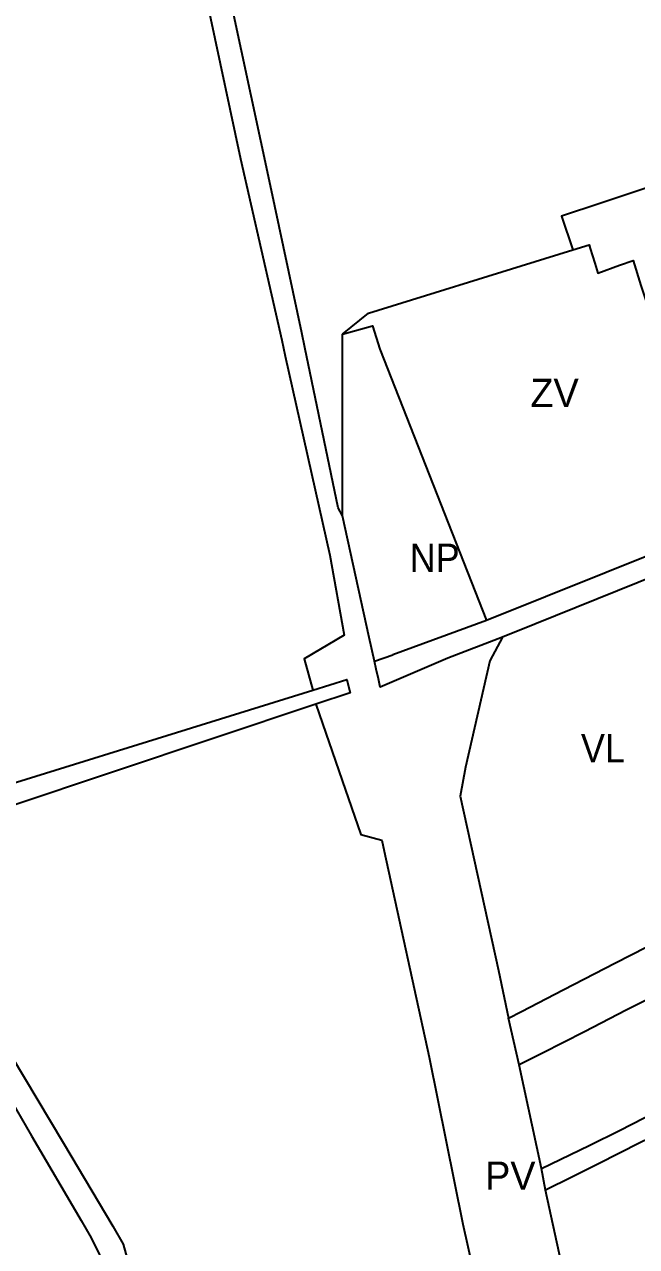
# Model space of a CAD drawing. Extents: x -650451 to -642268, y -1075216 to -1066610.
# Drawn here: x -648982 to -648658, y -1067753 to -1067105 of the extents above; entities that cross this region are included whole.
import ezdxf

# ---------------------------------------------------------------- set-up
doc = ezdxf.new("R2010")
doc.units = 0
doc.header["$LTSCALE"] = 6
doc.layers.add('1', color=7, linetype='Continuous', lineweight=35)
doc.layers.add('2', color=7, linetype='Continuous')
doc.layers.add('3', color=7, linetype='Continuous')

msp = doc.modelspace()

# ---------------------------------------------------------------- linework, layer by layer
at = {"layer": '1'}
for p, q in [((-648636.68, -1067380.92), (-648737.46, -1067421.52)), ((-648737.46, -1067421.52), (-648787.13, -1067439.58)), ((-648720.1, -1067657.12), (-648725.8, -1067632.36)), ((-648708.26, -1067712.07), (-648720.1, -1067657.12)), ((-648706.08, -1067723.56), (-648708.26, -1067712.07))]:
    msp.add_line(p, q, dxfattribs=at)
for points in [[(-648965.39, -1066723.15), (-648955.15, -1066770.11), (-648944.75, -1066815.41), (-648936.7, -1066852.52), (-648924.32, -1066909.55), (-648917.76, -1066942.65), (-648905.06, -1067006.7), (-648899.1, -1067033.34), (-648884.26, -1067099.63), (-648867.82, -1067176.66), (-648845.94, -1067272.85), (-648844.16, -1067281.37), (-648820.39, -1067386.83), (-648812.91, -1067429.16), (-648834.01, -1067441.81), (-648829.54, -1067458.42)], [(-648813.81, -1067365.91), (-648816.06, -1067361.71), (-648833.66, -1067276.77), (-648835.29, -1067268.93), (-648851.87, -1067191.04), (-648872.31, -1067095.5), (-648893.02, -1067002.5), (-648914.11, -1066907.05), (-648918.27, -1066888.41), (-648935.19, -1066812.53), (-648954.86, -1066720.16)], [(-649347.85, -1067077.78), (-649341.72, -1067086.34), (-649296.02, -1067150.21), (-649286.18, -1067163.62), (-649232.55, -1067236.73), (-649155.84, -1067339.24), (-649141.36, -1067361.14), (-649128.54, -1067392.42), (-649081.51, -1067517.84), (-649073.12, -1067526.28), (-649063.49, -1067529.27), (-649053.79, -1067527.97), (-648829.54, -1067458.42)], [(-648495.63, -1067161.363), (-648499.79, -1067162.97), (-648510.01, -1067144.84), (-648525.95, -1067150.5), (-648526.39, -1067149.8), (-648547.68, -1067156.93), (-648579.12, -1067167.45), (-648580.15, -1067164.76), (-648603.17, -1067172.45), (-648602.26, -1067175.2), (-648676.84, -1067200.16), (-648697.59, -1067207.11), (-648691.66, -1067224.94)], [(-648691.66, -1067224.94), (-648683.07, -1067222.28), (-648682.43, -1067224.18), (-648680.03, -1067231.91), (-648678.37, -1067237.22), (-648666.88, -1067233.11), (-648659.66, -1067230.53), (-648655.57, -1067243.76), (-648646.48, -1067271.25)], [(-648813.78, -1067269.55), (-648800.02, -1067258.42), (-648706.47, -1067229.51), (-648691.66, -1067224.94)], [(-648813.78, -1067269.55), (-648797.88, -1067265.22), (-648794.03, -1067277.5), (-648737.46, -1067421.52)], [(-648813.81, -1067365.91), (-648813.8, -1067322.02), (-648813.78, -1067269.55)], [(-648796.8, -1067443.1), (-648799.58, -1067430.4), (-648813.81, -1067365.91)], [(-648646.13, -1067396.91), (-648711.76, -1067423.39), (-648728.95, -1067430.33)], [(-648728.95, -1067430.33), (-648757.97, -1067441.51), (-648793.71, -1067456.88), (-648794.7, -1067452.46), (-648795.88, -1067447.21)], [(-648728.95, -1067430.33), (-648735.59, -1067442.88), (-648748.53, -1067499.3), (-648751.29, -1067514.57), (-648731.06, -1067607.06), (-648725.8, -1067632.36)], [(-648795.88, -1067447.21), (-648796.8, -1067443.1), (-648787.13, -1067439.58)], [(-648829.54, -1067458.42), (-648811.4, -1067452.79), (-648811.21, -1067453.52), (-648809.97, -1067458.52), (-648809.65, -1067459.77), (-648827.86, -1067465.86)], [(-648827.86, -1067465.86), (-649043.58, -1067537.95), (-649051.36, -1067541.81), (-649056.25, -1067548.45), (-649054.62, -1067560), (-649040.88, -1067579.35), (-649014.81, -1067616.11), (-648989.29, -1067652.07), (-648961.65, -1067698.67), (-648935.54, -1067742.7), (-648929.93, -1067752.22), (-648926.79, -1067763.65), (-648926.42, -1067773.69), (-648933.16, -1067786.77), (-648940.02, -1067793.41), (-648952.15, -1067802.08), (-649118.66, -1067906.86), (-649165.63, -1067937.14), (-649203.19, -1067963.4), (-649376.467, -1068081.552)], [(-648827.86, -1067465.86), (-648813.94, -1067506.27), (-648804.08, -1067534.88), (-648792.97, -1067537.86), (-648791.68, -1067543.78), (-648767.84, -1067652.98), (-648749.97, -1067741.49), (-648738.7, -1067792.04), (-648727.05, -1067844.33), (-648722.09, -1067863.84), (-648700.16, -1067963.42), (-648677.61, -1068061.74), (-648662.71, -1068124.76), (-648655.88, -1068153.63), (-648634.84, -1068248.76), (-648615.87, -1068327.3), (-648594.38, -1068425.02), (-648573.96, -1068518.34), (-648572.95, -1068522.97), (-648561.032, -1068578.982), (-648566.33, -1068582.22), (-648579.97, -1068587.39), (-648580.062, -1068590.087)], [(-648725.8, -1067632.36), (-648718.9, -1067628.79), (-648696.71, -1067617.33), (-648674.49, -1067605.85), (-648669.32, -1067603.18), (-648652.5, -1067594.5), (-648630.2, -1067582.97), (-648577.53, -1067555.77), (-648567.3, -1067550.48)], [(-648507.31, -1067548.84), (-648551.91, -1067571.47), (-648574.23, -1067582.89), (-648596.43, -1067594.35), (-648618.83, -1067605.54), (-648641.16, -1067616.88), (-648663.31, -1067628.15), (-648685.55, -1067639.55), (-648707.73, -1067650.94), (-648720.1, -1067657.12)], [(-648708.26, -1067712.07), (-648683.06, -1067699.88), (-648666.59, -1067691.63), (-648660.83, -1067688.75), (-648638.59, -1067677.44), (-648616.23, -1067666.06), (-648607.28, -1067661.48), (-648594.06, -1067654.71), (-648571.81, -1067643.31), (-648566.04, -1067640.39), (-648549.61, -1067632.06), (-648527.31, -1067620.61), (-648504.95, -1067609.19), (-648482.69, -1067597.72), (-648507.31, -1067548.84)], [(-648452.72, -1067657.62), (-648477.94, -1067607.47), (-648500.14, -1067618.94), (-648522.4, -1067630.35), (-648544.55, -1067641.82), (-648566.86, -1067653.13), (-648574.67, -1067657.12), (-648589.17, -1067664.52), (-648611.49, -1067675.9), (-648633.79, -1067687.24), (-648651.39, -1067696.1), (-648655.83, -1067698.33), (-648678.44, -1067709.73), (-648692.17, -1067716.68), (-648706.08, -1067723.56)], [(-648997.32, -1067662.6), (-648978.53, -1067694.76), (-648952.34, -1067739.61), (-648947.01, -1067748.74), (-648942.46, -1067757.73), (-648939.93, -1067764.54), (-648939.85, -1067770), (-648943.93, -1067777.06), (-648959.69, -1067793.21), (-649123.43, -1067894.75)], [(-648699.593, -1067840.046), (-648710.96, -1067789.91), (-648704.614, -1067788.491), (-648692.53, -1067785.79), (-648693.78, -1067780.24), (-648706.08, -1067723.56)]]:
    msp.add_lwpolyline(points, dxfattribs=at)

# ---------------------------------------------------------------- texts
at = {"layer": '2'}
msp.add_text('ZV', height=15, dxfattribs=at).set_placement((-648714.165, -1067308.312))
at = {"layer": '2', "width": 0.95}
for s, p in [('NP', (-648778.1, -1067395.733)), ('VL', (-648687.36, -1067496.685))]:
    msp.add_text(s, height=15, dxfattribs=at).set_placement(p)
at = {"layer": '3'}
msp.add_text('PV', height=15, dxfattribs=at).set_placement((-648738.171, -1067723.333))

doc.saveas('drawing.dxf')
